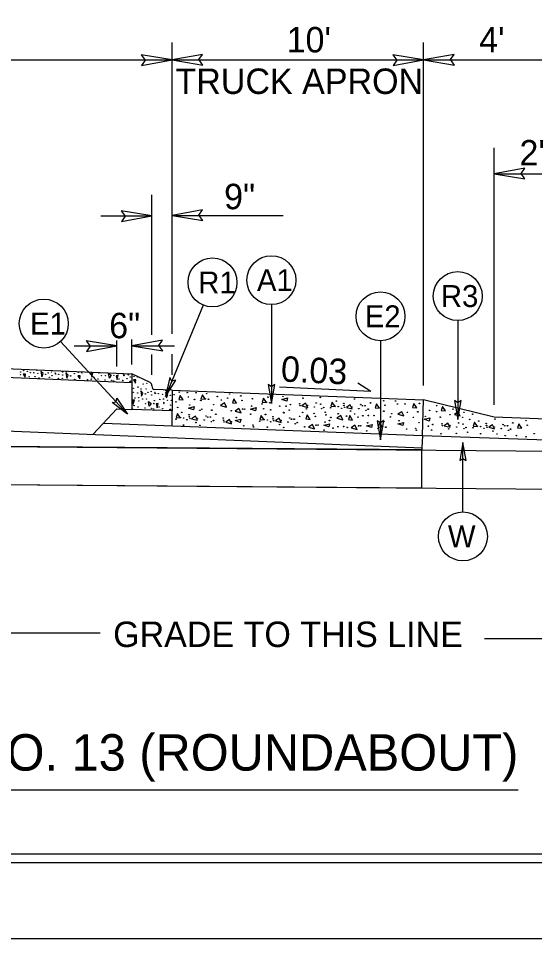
# Model space of a CAD drawing. Extents: x 573748 to 574632, y -54663 to -53209.
# Drawn here: x 574096.8 to 574127.2, y -54603.6 to -54549.4 of the extents above; entities that cross this region are included whole.
import ezdxf

# ---------------------------------------------------------------- set-up
doc = ezdxf.new("R2010")
doc.units = 0
for name, color, linetype in [('Prop Dimension', 7, 'Continuous'), ('Prop Dimension Text', 7, 'Continuous'), ('Prop Rem of Exist Asph Pvmt', 7, 'Continuous'), ('Prop Terminator CELL', 7, 'Continuous'), ('Sheet Cutting Line CELL', 7, 'Continuous'), ('Sheet Plot Border Inside CELL', 7, 'Continuous'), ('Sheet Plot Border Outside CELL', 7, 'Continuous'), ('Sheet Typical CELL', 7, 'Continuous'), ('Typical Arrow Superelevation CELL', 7, 'Continuous'), ('Typical Curb CELL', 7, 'Continuous'), ('Typical ID Circle CELL', 7, 'Continuous'), ('Typical Pavement Slope CELL', 7, 'Continuous'), ('Typical Terminator CELL', 7, 'Continuous'), ('Typical Text ID Circle CELL', 7, 'Continuous'), ('Typical Text Label CELL', 7, 'Continuous')]:
    doc.layers.add(name, color=color, linetype=linetype)

msp = doc.modelspace()

# ---------------------------------------------------------------- linework, layer by layer
at = {"layer": 'Prop Dimension'}
for p, q in [((574105.83, -54567.983), (574105.83, -54550.814)), ((574120.665, -54571.038), (574120.665, -54550.814)), ((574030.665, -54551.839), (574105.83, -54551.839)), ((574105.83, -54551.839), (574120.665, -54551.839)), ((574120.665, -54551.839), (574129.029, -54551.839)), ((574124.824, -54572.181), (574124.824, -54557.025)), ((574124.824, -54558.544), (574129.029, -54558.544)), ((574104.643, -54568.043), (574104.643, -54559.8)), ((574101.631, -54561.022), (574104.643, -54561.022)), ((574105.83, -54561.002), (574112.391, -54561.002)), ((574102.578, -54569.908), (574102.578, -54568.386)), ((574103.469, -54569.804), (574103.469, -54568.327)), ((574100.067, -54568.701), (574102.578, -54568.701)), ((574103.469, -54568.701), (574105.974, -54568.701)), ((574104.643, -54570.397), (574104.643, -54569.207)), ((574105.83, -54570.397), (574105.83, -54569.192)), ((574029.942, -54574.073), (574136.935, -54574.974)), ((574029.942, -54576.31), (574136.935, -54577.21))]:
    msp.add_line(p, q, dxfattribs=at)
for points in [[(574101.602, -54585.645), (574092.058, -54585.645), (574072.28, -54572.729)], [(574124.244, -54585.952), (574134.095, -54585.952), (574141.412, -54575.744)]]:
    msp.add_lwpolyline(points, dxfattribs=at)
at = {"layer": 'Prop Rem of Exist Asph Pvmt'}
for p, q in [((574120.562, -54574.836), (574029.942, -54574.073)), ((574120.562, -54577.072), (574120.562, -54574.836)), ((574029.942, -54576.31), (574120.562, -54577.072))]:
    msp.add_line(p, q, dxfattribs=at)
at = {"layer": 'Prop Terminator CELL'}
for points in [[(574104.034, -54552.172), (574105.83, -54551.839), (574104.016, -54551.542), (574104.25, -54551.859)], [(574107.627, -54551.506), (574105.83, -54551.839), (574107.645, -54552.136), (574107.411, -54551.818)], [(574118.868, -54552.172), (574120.665, -54551.839), (574118.85, -54551.542), (574119.084, -54551.859)], [(574122.461, -54551.506), (574120.665, -54551.839), (574122.479, -54552.136), (574122.245, -54551.818)], [(574126.621, -54558.211), (574124.824, -54558.544), (574126.639, -54558.841), (574126.405, -54558.524)], [(574102.846, -54561.355), (574104.643, -54561.022), (574102.828, -54560.725), (574103.062, -54561.042)], [(574107.627, -54560.669), (574105.83, -54561.002), (574107.645, -54561.299), (574107.411, -54560.982)], [(574100.782, -54569.034), (574102.578, -54568.701), (574100.764, -54568.404), (574100.998, -54568.721)], [(574105.265, -54568.367), (574103.469, -54568.701), (574105.283, -54568.997), (574105.049, -54568.68)]]:
    msp.add_lwpolyline(points, close=True, dxfattribs=at)
at = {"layer": 'Sheet Cutting Line CELL'}
msp.add_line((573944.171, -54603.647), (574280.971, -54603.647), dxfattribs=at)
at = {"layer": 'Sheet Plot Border Inside CELL'}
msp.add_lwpolyline([(574280.071, -54388.137), (573946.771, -54388.137), (573946.771, -54599.157), (574280.071, -54599.157)], close=True, dxfattribs=at)
at = {"layer": 'Sheet Plot Border Outside CELL'}
msp.add_lwpolyline([(574280.971, -54383.647), (573944.171, -54383.647), (573944.171, -54603.647), (574280.971, -54603.647)], close=True, dxfattribs=at)
at = {"layer": 'Sheet Typical CELL'}
msp.add_lwpolyline([(574277.571, -54388.647), (573977.571, -54388.647), (573977.571, -54598.647), (574277.571, -54598.647)], close=True, dxfattribs=at)
at = {"layer": 'Typical Arrow Superelevation CELL'}
for q in [(574112.167, -54571.132), (574116.785, -54570.892)]:
    msp.add_line((574117.555, -54571.386), q, dxfattribs=at)
at = {"layer": 'Typical Curb CELL'}
for p, q in [((574097.19, -54570.369), (574097.052, -54570.363)), ((574097.052, -54570.363), (574097.175, -54570.549)), ((574097.175, -54570.549), (574097.19, -54570.369)), ((574098.106, -54570.205), (574098.161, -54570.521)), ((574098.233, -54570.332), (574098.106, -54570.205)), ((574098.161, -54570.521), (574098.233, -54570.332)), ((574099.574, -54570.293), (574099.629, -54570.607)), ((574099.701, -54570.421), (574099.574, -54570.293)), ((574099.629, -54570.607), (574099.701, -54570.421)), ((574100.41, -54570.462), (574100.273, -54570.457)), ((574100.273, -54570.457), (574100.396, -54570.642)), ((574100.396, -54570.642), (574100.41, -54570.462)), ((574101.172, -54570.288), (574101.055, -54570.313)), ((574101.055, -54570.313), (574101.105, -54570.544)), ((574101.105, -54570.544), (574101.172, -54570.288)), ((574102.096, -54570.324), (574102.236, -54570.433)), ((574102.136, -54570.6), (574102.096, -54570.324)), ((574102.236, -54570.433), (574102.136, -54570.6)), ((574102.659, -54570.434), (574102.542, -54570.459)), ((574102.542, -54570.459), (574102.592, -54570.689)), ((574102.592, -54570.689), (574102.659, -54570.434)), ((574104.547, -54570.859), (574103.469, -54570.338)), ((574103.469, -54570.338), (574103.469, -54572.439)), ((574103.69, -54570.707), (574103.553, -54570.702)), ((574103.553, -54570.702), (574103.676, -54570.887)), ((574103.676, -54570.887), (574103.69, -54570.707)), ((574104.642, -54571.06), (574104.643, -54571.049)), ((574103.983, -54571.354), (574104.038, -54571.67)), ((574104.11, -54571.482), (574103.983, -54571.354)), ((574104.038, -54571.67), (574104.11, -54571.482)), ((574105.834, -54571.302), (574104.785, -54571.263)), ((574105.451, -54571.442), (574105.506, -54571.756)), ((574105.578, -54571.57), (574105.451, -54571.442)), ((574105.506, -54571.756), (574105.578, -54571.57)), ((574105.834, -54571.302), (574105.834, -54572.528)), ((574106.311, -54571.625), (574106.23, -54571.861)), ((574106.483, -54571.883), (574106.311, -54571.625)), ((574107.619, -54571.579), (574107.539, -54571.814)), ((574107.79, -54571.837), (574107.619, -54571.579)), ((574103.616, -54571.874), (574103.499, -54571.899)), ((574103.499, -54571.899), (574103.549, -54572.129)), ((574103.549, -54572.129), (574103.616, -54571.874)), ((574104.452, -54571.979), (574104.592, -54572.088)), ((574104.493, -54572.255), (574104.452, -54571.979)), ((574104.592, -54572.088), (574104.493, -54572.255)), ((574105.015, -54572.089), (574104.899, -54572.114)), ((574104.899, -54572.114), (574104.949, -54572.345)), ((574104.949, -54572.345), (574105.015, -54572.089)), ((574106.23, -54571.861), (574106.483, -54571.883)), ((574107.539, -54571.814), (574107.79, -54571.837)), ((574108.918, -54572.062), (574108.696, -54572.212)), ((574108.696, -54572.212), (574109.04, -54572.308)), ((574109.04, -54572.308), (574108.918, -54572.062)), ((574109.469, -54571.824), (574109.388, -54572.06)), ((574109.388, -54572.06), (574109.641, -54572.082)), ((574109.641, -54572.082), (574109.469, -54571.824)), ((574111.229, -54571.785), (574111.148, -54572.021)), ((574111.148, -54572.021), (574111.399, -54572.043)), ((574111.399, -54572.043), (574111.229, -54571.785)), ((574112.308, -54571.849), (574112.635, -54571.767)), ((574112.593, -54571.956), (574112.308, -54571.849)), ((574112.635, -54571.767), (574112.593, -54571.956)), ((574113.707, -54572.075), (574113.485, -54572.225)), ((574113.485, -54572.225), (574113.83, -54572.321)), ((574113.83, -54572.321), (574113.707, -54572.075)), ((574115.268, -54572.014), (574115.188, -54572.25)), ((574115.188, -54572.25), (574115.439, -54572.272)), ((574115.439, -54572.272), (574115.268, -54572.014)), ((574116.329, -54572.171), (574116.107, -54572.321)), ((574116.451, -54572.416), (574116.329, -54572.171)), ((574117.89, -54572.11), (574117.809, -54572.346)), ((574118.062, -54572.368), (574117.89, -54572.11)), ((574120.092, -54572.098), (574120.011, -54572.334)), ((574120.264, -54572.356), (574120.092, -54572.098)), ((574120.588, -54573.979), (574120.665, -54571.88)), ((574124.824, -54572.904), (574120.665, -54571.88)), ((574105.834, -54572.528), (574103.469, -54572.439)), ((574106.149, -54572.685), (574106.068, -54572.92)), ((574106.319, -54572.942), (574106.149, -54572.685)), ((574106.81, -54572.361), (574107.137, -54572.279)), ((574107.095, -54572.468), (574106.81, -54572.361)), ((574107.137, -54572.279), (574107.095, -54572.468)), ((574109.776, -54572.392), (574109.554, -54572.542)), ((574109.554, -54572.542), (574109.898, -54572.637)), ((574109.898, -54572.637), (574109.776, -54572.392)), ((574110.458, -54572.423), (574110.785, -54572.34)), ((574110.743, -54572.529), (574110.458, -54572.423)), ((574110.785, -54572.34), (574110.743, -54572.529)), ((574111.087, -54572.806), (574111.007, -54573.041)), ((574111.258, -54573.064), (574111.087, -54572.806)), ((574113.798, -54572.771), (574113.717, -54573.007)), ((574113.97, -54573.029), (574113.798, -54572.771)), ((574115.778, -54572.805), (574115.555, -54572.954)), ((574115.9, -54573.05), (574115.778, -54572.805)), ((574116.107, -54572.321), (574116.451, -54572.416)), ((574117.809, -54572.346), (574118.062, -54572.368)), ((574119.37, -54572.584), (574119.148, -54572.733)), ((574119.148, -54572.733), (574119.493, -54572.829)), ((574119.493, -54572.829), (574119.37, -54572.584)), ((574120.011, -54572.334), (574120.264, -54572.356)), ((574121.784, -54572.275), (574121.703, -54572.511)), ((574121.703, -54572.511), (574121.956, -54572.533)), ((574121.956, -54572.533), (574121.784, -54572.275)), ((574122.701, -54572.586), (574122.479, -54572.735)), ((574122.479, -54572.735), (574122.823, -54572.831)), ((574122.823, -54572.831), (574122.701, -54572.586)), ((574106.068, -54572.92), (574106.319, -54572.942)), ((574107.21, -54572.841), (574106.987, -54572.991)), ((574106.987, -54572.991), (574107.332, -54573.087)), ((574107.332, -54573.087), (574107.21, -54572.841)), ((574109.222, -54573.041), (574109, -54573.191)), ((574109, -54573.191), (574109.345, -54573.287)), ((574109.345, -54573.287), (574109.222, -54573.041)), ((574109.557, -54573.099), (574109.884, -54573.017)), ((574109.842, -54573.206), (574109.557, -54573.099)), ((574109.884, -54573.017), (574109.842, -54573.206)), ((574111.007, -54573.041), (574111.258, -54573.064)), ((574112.148, -54572.962), (574111.926, -54573.112)), ((574111.926, -54573.112), (574112.27, -54573.208)), ((574112.27, -54573.208), (574112.148, -54572.962)), ((574113.717, -54573.007), (574113.97, -54573.029)), ((574114.105, -54573.339), (574113.882, -54573.489)), ((574114.227, -54573.584), (574114.105, -54573.339)), ((574114.786, -54573.37), (574115.113, -54573.287)), ((574115.113, -54573.287), (574115.071, -54573.476)), ((574115.555, -54572.954), (574115.9, -54573.05)), ((574116.307, -54572.812), (574116.227, -54573.047)), ((574116.227, -54573.047), (574116.48, -54573.07)), ((574116.48, -54573.07), (574116.307, -54572.812)), ((574117.296, -54573.41), (574117.623, -54573.328)), ((574117.623, -54573.328), (574117.581, -54573.517)), ((574118.072, -54573.227), (574117.991, -54573.463)), ((574118.242, -54573.485), (574118.072, -54573.227)), ((574119.151, -54573.291), (574119.478, -54573.209)), ((574119.436, -54573.398), (574119.151, -54573.291)), ((574119.478, -54573.209), (574119.436, -54573.398)), ((574120.7, -54573.027), (574121.027, -54572.945)), ((574120.985, -54573.134), (574120.7, -54573.027)), ((574121.027, -54572.945), (574120.985, -54573.134)), ((574122.099, -54573.253), (574121.877, -54573.403)), ((574122.221, -54573.499), (574122.099, -54573.253)), ((574123.66, -54573.192), (574123.579, -54573.428)), ((574123.83, -54573.45), (574123.66, -54573.192)), ((574124.721, -54573.349), (574124.498, -54573.499)), ((574124.843, -54573.594), (574124.721, -54573.349)), ((574129.029, -54573.062), (574124.824, -54572.904)), ((574126.282, -54573.288), (574126.201, -54573.524)), ((574126.454, -54573.546), (574126.282, -54573.288)), ((574113.882, -54573.489), (574114.227, -54573.584)), ((574115.071, -54573.476), (574114.786, -54573.37)), ((574116.614, -54573.379), (574116.392, -54573.529)), ((574116.392, -54573.529), (574116.736, -54573.625)), ((574116.736, -54573.625), (574116.614, -54573.379)), ((574117.581, -54573.517), (574117.296, -54573.41)), ((574117.991, -54573.463), (574118.242, -54573.485)), ((574121.877, -54573.403), (574122.221, -54573.499)), ((574123.579, -54573.428), (574123.83, -54573.45)), ((574124.498, -54573.499), (574124.843, -54573.594)), ((574126.201, -54573.524), (574126.454, -54573.546)), ((574120.588, -54573.979), (574128.984, -54574.286))]:
    msp.add_line(p, q, dxfattribs=at)
for centre in [(574105.953, -54571.575), (574106.256, -54571.424), (574106.73, -54571.446), (574106.8, -54571.712), (574107.248, -54571.459), (574107.873, -54571.517), (574108.501, -54571.683), (574109.232, -54571.534), (574109.888, -54571.645), (574111.482, -54571.723), (574112.374, -54571.672), (574114.572, -54571.734), (574106.064, -54572.001), (574106.876, -54572.184), (574107.155, -54571.852), (574107.53, -54571.913), (574107.786, -54571.816), (574107.982, -54571.843), (574108.287, -54572.165), (574108.742, -54571.888), (574109.111, -54571.774), (574109.958, -54571.911), (574110.523, -54572.246), (574110.573, -54571.813), (574111.139, -54572.119), (574111.395, -54572.022), (574111.591, -54572.049), (574112.177, -54572.246), (574112.557, -54572.253), (574112.813, -54572.156), (574113.354, -54572.115), (574113.386, -54572.223), (574113.545, -54571.78), (574113.818, -54572.204), (574114.33, -54572.063), (574114.592, -54572.132), (574115.435, -54572.251), (574115.522, -54571.952), (574115.631, -54572.278), (574115.959, -54572.086), (574115.976, -54572.211), (574116.589, -54571.827), (574116.953, -54572.159), (574117.055, -54572.226), (574117.214, -54572.228), (574117.532, -54572.06), (574118.309, -54571.931), (574118.379, -54572.197), (574119.005, -54571.95), (574119.124, -54572.124), (574119.572, -54572.12), (574120.42, -54572.09), (574121.426, -54572.225), (574106.165, -54572.324), (574106.403, -54572.622), (574106.84, -54572.756), (574107.469, -54572.498), (574107.583, -54572.433), (574108.18, -54572.487), (574108.413, -54572.73), (574109.323, -54572.522), (574109.992, -54572.426), (574110.113, -54572.423), (574110.469, -54572.722), (574111.231, -54572.403), (574111.341, -54572.743), (574111.646, -54572.469), (574112.408, -54572.619), (574112.434, -54572.65), (574112.741, -54572.483), (574113.53, -54572.621), (574113.751, -54572.416), (574114.201, -54572.679), (574114.223, -54572.302), (574114.651, -54572.401), (574114.772, -54572.333), (574114.866, -54572.611), (574114.902, -54572.761), (574115.179, -54572.348), (574115.627, -54572.7), (574115.829, -54572.382), (574116.008, -54572.318), (574116.357, -54572.543), (574116.441, -54572.3), (574116.595, -54572.715), (574116.845, -54572.397), (574117.081, -54572.815), (574117.274, -54572.496), (574117.394, -54572.429), (574117.411, -54572.801), (574117.743, -54572.808), (574118.317, -54572.547), (574118.787, -54572.693), (574119.707, -54572.615), (574120.32, -54572.586), (574121.012, -54572.504), (574121.427, -54572.57), (574122.215, -54572.752), (574122.396, -54572.423), (574123.038, -54572.617), (574123.553, -54572.723), (574106.06, -54573.019), (574106.315, -54572.922), (574106.511, -54572.949), (574106.709, -54573.052), (574106.857, -54572.881), (574106.889, -54572.989), (574107.237, -54573.214), (574107.321, -54572.971), (574107.726, -54573.068), (574107.833, -54572.829), (574107.936, -54572.897), (574108.095, -54572.898), (574108.154, -54573.167), (574108.275, -54573.1), (574108.853, -54572.956), (574108.87, -54573.081), (574108.901, -54573.188), (574109.334, -54573.17), (574109.623, -54572.922), (574110.603, -54573.366), (574110.998, -54573.14), (574111.254, -54573.043), (574111.449, -54573.07), (574111.648, -54573.173), (574111.778, -54572.877), (574111.795, -54573.003), (574111.827, -54573.11), (574112.176, -54573.335), (574112.26, -54573.092), (574112.664, -54573.189), (574112.772, -54572.95), (574112.874, -54573.018), (574113.033, -54573.019), (574113.093, -54573.288), (574113.213, -54573.221), (574113.351, -54572.851), (574114.287, -54572.858), (574114.852, -54573.193), (574115.114, -54573.104), (574115.194, -54572.914), (574116.115, -54572.836), (574116.796, -54572.898), (574117.362, -54573.233), (574118.326, -54573.165), (574118.707, -54572.883), (574119.217, -54573.114), (574120.063, -54572.913), (574120.388, -54573.222), (574120.766, -54572.85), (574121.204, -54573.334), (574121.644, -54572.901), (574121.746, -54573.293), (574122.722, -54573.241), (574122.964, -54572.912), (574122.984, -54573.31), (574123.379, -54573.036), (574123.914, -54573.13), (574124.351, -54573.264), (574124.875, -54573.014), (574125.344, -54573.337), (574125.924, -54573.238), (574126.701, -54573.109), (574106.508, -54573.371), (574107.476, -54573.386), (574110.061, -54573.406), (574110.635, -54573.473), (574111.446, -54573.492), (574112.414, -54573.507), (574113.651, -54573.469), (574114.321, -54573.373), (574114.442, -54573.37), (574114.798, -54573.669), (574115.328, -54573.549), (574115.612, -54573.466), (574115.943, -54573.452), (574116.161, -54573.51), (574116.83, -54573.413), (574116.951, -54573.41), (574117.307, -54573.709), (574117.982, -54573.562), (574118.238, -54573.465), (574118.434, -54573.491), (574119.656, -54573.598), (574120.197, -54573.558), (574120.229, -54573.665), (574120.948, -54573.431), (574121.133, -54573.661), (574121.688, -54573.88), (574121.778, -54573.401), (574122.142, -54573.594), (574122.21, -54573.383), (574122.593, -54573.857), (574122.615, -54573.48), (574123.043, -54573.579), (574123.163, -54573.511), (574123.258, -54573.789), (574123.571, -54573.526), (574123.826, -54573.429), (574124.019, -54573.878), (574124.022, -54573.456), (574124.22, -54573.56), (574124.368, -54573.389), (574124.4, -54573.496), (574124.749, -54573.721), (574124.832, -54573.478), (574124.987, -54573.893), (574125.237, -54573.575), (574125.447, -54573.405), (574125.606, -54573.406), (574125.665, -54573.675), (574125.786, -54573.607), (574126.77, -54573.375), (574127.179, -54573.871), (574125.472, -54573.993), (574126.135, -54573.986), (574126.702, -54574.056)]:
    msp.add_circle(centre, 0.0168, dxfattribs=at)
for centre in [(574096.898, -54570.4), (574096.905, -54570.235), (574097.091, -54570.16), (574097.297, -54570.192), (574097.41, -54570.517), (574097.472, -54570.279), (574097.684, -54570.284), (574097.753, -54570.516), (574097.864, -54570.145), (574097.922, -54570.321), (574097.984, -54570.599), (574098.383, -54570.377), (574098.531, -54570.287), (574098.594, -54570.558), (574098.728, -54570.238), (574098.756, -54570.448), (574098.943, -54570.293), (574098.965, -54570.355), (574099.131, -54570.613), (574099.153, -54570.372), (574099.363, -54570.613), (574099.382, -54570.228), (574099.39, -54570.409), (574099.613, -54570.227), (574099.851, -54570.464), (574100.076, -54570.334), (574100.312, -54570.253), (574100.518, -54570.286), (574101.234, -54570.558), (574101.462, -54570.651), (574101.519, -54570.293), (574101.676, -54570.459), (574101.911, -54570.45), (574102.403, -54570.44), (574102.635, -54570.345), (574102.702, -54570.645), (574102.987, -54570.381), (574102.995, -54570.444), (574103.179, -54570.629), (574103.257, -54570.401), (574103.379, -54570.538), (574103.592, -54570.498), (574103.798, -54570.531), (574100.09, -54570.671), (574100.85, -54570.697), (574101.068, -54570.657), (574101.879, -54570.705), (574102.269, -54570.729), (574102.391, -54570.762), (574102.93, -54570.739), (574103.347, -54570.793), (574103.392, -54570.779), (574103.819, -54571.13), (574104.13, -54570.942), (574104.348, -54570.902), (574103.556, -54571.205), (574103.561, -54571.433), (574103.799, -54571.471), (574104.003, -54571.241), (574104.26, -54571.526), (574104.306, -54571.243), (574104.408, -54571.436), (574104.605, -54571.387), (574104.633, -54571.597), (574104.82, -54571.442), (574104.843, -54571.504), (574105.03, -54571.521), (574105.267, -54571.558), (574105.471, -54571.329), (574105.728, -54571.614), (574103.59, -54572.213), (574103.643, -54571.768), (574103.861, -54571.748), (574103.875, -54571.948), (574104.097, -54571.823), (574104.267, -54572.105), (574104.328, -54571.823), (574104.759, -54572.095), (574104.791, -54571.93), (574105.111, -54571.856), (574105.329, -54571.836), (574105.343, -54572.036), (574105.351, -54572.099), (574105.565, -54571.911), (574105.735, -54572.193), (574105.797, -54571.911), (574103.818, -54572.307), (574104.236, -54572.36), (574104.625, -54572.384), (574104.747, -54572.417), (574105.059, -54572.301), (574105.286, -54572.395), (574105.704, -54572.448), (574105.749, -54572.434)]:
    msp.add_ellipse(centre, major_axis=(0.0005, 0.0133), ratio=0.761905, dxfattribs=at)
for centre, major_axis, start_param, end_param in [((574104.493, -54571.044), (0.007, 0.197), 4.712389, 5.961435), ((574104.792, -54571.066), (-0.007, -0.197), 4.712389, 6.283185), ((574103.504, -54572.428), (0.0005, 0.0133), 5.184301, 7.404412)]:
    msp.add_ellipse(centre, major_axis=major_axis, ratio=0.761905, start_param=start_param, end_param=end_param, dxfattribs=at)
at = {"layer": 'Typical ID Circle CELL'}
for p, q in [((574107.669, -54566.29), (574105.447, -54571.685)), ((574111.687, -54566.265), (574111.687, -54572.099)), ((574122.672, -54567.205), (574122.672, -54573.039)), ((574099.251, -54568.444), (574103.208, -54572.731)), ((574118.121, -54568.398), (574118.121, -54574.232)), ((574122.981, -54578.488), (574122.981, -54574.404))]:
    msp.add_line(p, q, dxfattribs=at)
for centre in [(574108.218, -54564.956), (574111.687, -54564.822), (574122.672, -54565.762), (574118.121, -54566.955), (574098.272, -54567.384), (574122.981, -54579.93)]:
    msp.add_circle(centre, 1.443, dxfattribs=at)
at = {"layer": 'Typical Pavement Slope CELL'}
for p, q in [((574030.668, -54567.336), (574103.469, -54570.338)), ((574030.665, -54567.85), (574103.469, -54570.852)), ((574030.665, -54571.026), (574120.562, -54574.704)), ((574105.834, -54571.302), (574120.665, -54571.88)), ((574101.176, -54573.911), (574102.578, -54572.406)), ((574102.578, -54572.406), (574103.469, -54572.439)), ((574105.834, -54573.404), (574105.834, -54572.528)), ((574101.795, -54573.246), (574120.588, -54573.979)), ((574120.588, -54573.979), (574120.562, -54574.704)), ((574120.562, -54574.704), (574120.562, -54574.836))]:
    msp.add_line(p, q, dxfattribs=at)
at = {"layer": 'Typical Terminator CELL'}
for points in [[(574105.697, -54570.571), (574105.447, -54571.685), (574106.063, -54570.715), (574105.823, -54570.772)], [(574111.494, -54570.974), (574111.687, -54572.099), (574111.887, -54570.968), (574111.687, -54571.112)], [(574102.587, -54571.773), (574103.208, -54572.731), (574102.294, -54572.035), (574102.538, -54572.005)], [(574122.479, -54571.914), (574122.672, -54573.039), (574122.872, -54571.908), (574122.672, -54572.052)], [(574117.927, -54573.107), (574118.121, -54574.232), (574118.321, -54573.1), (574118.121, -54573.244)], [(574123.162, -54575.459), (574122.981, -54574.404), (574122.793, -54575.465), (574122.981, -54575.33)]]:
    msp.add_lwpolyline(points, close=True, dxfattribs=at)
at = {"layer": 'Typical Text Label CELL'}
msp.add_line((574067.816, -54594.87), (574126.242, -54594.87), dxfattribs=at)

# ---------------------------------------------------------------- texts
at = {"layer": 'Prop Dimension'}
msp.add_text('GRADE TO THIS LINE', height=1.5, rotation=360, dxfattribs=at).set_placement((574102.36, -54586.453))
at = {"layer": 'Prop Dimension Text'}
for s, height, p in [("10'", 1.5, (574112.586, -54551.393)), ("4'", 1.5, (574123.937, -54551.394)), ('TRUCK APRON', 1.5, (574106.035, -54553.842)), ("2'", 1.5, (574126.314, -54558.059)), ('9"', 1.5, (574108.902, -54560.639)), ('6"', 1.5, (574102.126, -54568.247)), ('TYPICAL SECTION NO. 13 (ROUNDABOUT)', 2.14841, (574067.663, -54593.742))]:
    msp.add_text(s, height=height, dxfattribs=at).set_placement(p)
msp.add_text('0.03', height=1.5, rotation=357.2997, dxfattribs=at).set_placement((574112.225, -54570.792))
at = {"layer": 'Typical Text ID Circle CELL'}
for s, height, p in [('R1', 1.2912, (574107.376, -54565.603)), ('A1', 1.2912, (574110.837, -54565.465)), ('R3', 1.2912, (574121.681, -54566.405)), ('E2', 1.2912, (574117.195, -54567.598)), ('E1', 1.2912, (574097.464, -54568.027)), ('W', 1.291, (574122.096, -54580.573))]:
    msp.add_text(s, height=height, dxfattribs=at).set_placement(p)

doc.saveas('drawing.dxf')
